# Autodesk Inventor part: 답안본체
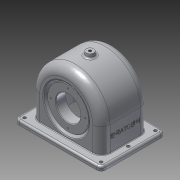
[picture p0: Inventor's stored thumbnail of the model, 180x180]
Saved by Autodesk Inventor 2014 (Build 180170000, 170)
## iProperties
Created: 2015-09
Part Number: 답안본체
Material: 알루미늄 6061
Document SubType Name: Modeling
Designer: basic
Density: 2.71 g/cm^3
Appearance: 알루미늄 - 평지
Mass: 723.087 g
Surface Area: 889.802 cm^2
Volume: 266.822 cm^3
Author: basic
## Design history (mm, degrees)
sketch "스케치2"
  geometry: L1 (57, 47)-(57, 0); L2 (-57, 47)-(-57, 0); L3 (-57, 0)-(57, 0); A1 r 57 centre (0, 47) between (57, 47) and (-57, 47); 2 further points
  constraints: 6 end point, 2 coincident, 2 point on circle, 2 tangent, 1 centre point, 1 midpoint, 1 parallel, 1 perpendicular, 1 vertical
  dimensions: "d1" = 47 distance from line of L3 A1.centre; "d2" = 104 dimension on A1 L3
extrude "돌출1" new body sketch "스케치2" stored distance "d3" = 77; taper "d4" = 0 deg
sketch "스케치3"
  geometry: L1 (114, -77)-(114, 0) reference; L2 (0, 0)-(114, 0) reference; L3 (0, -77)-(0, 0) reference; L4 (114, -77)-(0, -77) reference; L5 (-13, 13.5)-(127, 13.5); L6 (127, 13.5)-(127, -90.5); L7 (127, -90.5)-(-13, -90.5); L8 (-13, -90.5)-(-13, 13.5); 3 further points
  constraints: 8 end point, 2 midpoint, 2 parallel, 1 horizontal, 1 horizontal alignment, 1 perpendicular, 1 vertical alignment
  dimensions: "d6" = 140 distance of L5.start L5.end; "d7" = 104 distance of L5.end L6.end
extrude "돌출2" join sketch "스케치3" distance "d8" = 7; taper "d9" = 0 deg
node "작업 평면1"
sketch "스케치4"
  geometry: C1 r 6 at (-70, -52); 1 further point
  constraints: 1 centre point, 1 coincident
  dimensions: "d11" = 12 diameter of C1
extrude "돌출3" join sketch "스케치4" distance "d12" = 7; taper "d13" = 10 deg
sketch "스케치5"
  geometry: C1 r 31 at (0, -47); A1 r 57 centre (0, -47) between (-57, -47) and (57, -47) reference; 1 further point
  constraints: 1 centre point, 1 coincident
  dimensions: "d14" = 62 diameter of C1
extrude "돌출4" join sketch "스케치5" distance "d15" = 10; taper "d16" = 0 deg
fillet "모깎기1" dims "d17" = 7
sketch "스케치6"
  geometry: L1 (-127, 6.5)-(-127, -83.5) reference; L2 (-120, -90.5)-(6, -90.5) reference; L3 (13, -83.5)-(13, 6.5) reference; 7 further points
  constraints: 4 vertical alignment, 3 horizontal alignment
  dimensions: "d18" = 8 distance from line of L2 point (-119, -82.5); "d19" = 44 distance of point (-119, -38.5) point (-119, -82.5); "d20" = 44 distance of point (-119, 5.5) point (-119, -38.5); "d21" = 8 distance from line of L1 point (-119, 5.5); "d22" = 8 distance from line of L3 point (5, -82.5)
hole "구멍1" sketch "스케치6" at (-119, 5.5), (5, 5.5), (5, -38.5), (5, -82.5), (-119, -82.5), (-119, -38.5) diameter "d23" = 5; stored, may be unused: countersink angle "d27" = 90 deg, drill point angle "d29" = 118 deg; dims "d24" = 6, "d25" = 4, "d26" = 2, "d28" = 8
hole "구멍2" diameter "d32" = 4.459; stored, may be unused: countersink angle "d36" = 90 deg, drill point angle "d38" = 118 deg; dims "d33" = 6, "d34" = 4, "d35" = 2, "d37" = 8, "d39" = 10, "d40" = 10
node "작업 평면2"
sketch "스케치10"
  geometry: L1 (-51, 47)-(-51, 0); L2 (51, 47)-(51, 0); L3 (63, 0)-(-63, 0) reference; L4 (-57, 7)-(-57, 47) reference; A1 r 57 centre (0, 47) between (57, 47) and (-57, 47) reference; A2 r 51 centre (0, 47) between (51, 47) and (-51, 47); 1 further point
  constraints: 4 end point, 2 point on circle, 2 point on line, 2 tangent, 1 centre point, 1 parallel, 1 vertical
  dimensions: "d51" = 51 radius of A2
extrude "돌출6" cut sketch "스케치10" stored distance "d52" = 67; taper "d53" = 0 deg
node "작업 평면3"
sketch "스케치11"
  geometry: C1 r 28 at (0, 47); 1 further point
  constraints: 1 centre point, 1 vertical alignment
  dimensions: "d55" = 56 diameter of C1; "d56" = 47 distance of point (0, 0) C1.centre
extrude "돌출7" join sketch "스케치11" stored distance "d57" = 67; taper "d58" = 40 deg
sketch "스케치13"
  geometry: L1 (-19.5, 75)-(-33.5, 86.747) reference; L2 (-38.5, 104)-(-38.5, 47) reference; L3 (-38.5, 47)-(-38.5, 7) reference; L4 (-38.5, 47)-(-35.5, 47); L5 (-35.5, 47)-(-35.5, 80); L6 (-33.833, 80.5)-(-38.5, 84.416); L7 (-35.5, 80)-(-33.833, 80); L8 (-33.833, 80)-(-33.833, 80.5); 1 further point
  constraints: 10 end point, 3 perpendicular, 1 parallel, 1 point on line
  dimensions: "d64" = 3 distance between parallel lines of L2 L5; "d65" = 5 distance between parallel lines of L1 L6; "d66" = 66 diameter of L7 L4; "d67" = 0.5 distance of L7.end L6.start
revolve "회전1" sketch "스케치13" stored, may be unused: angle "d68" = 90 deg
fillet "모깎기2" dims "d69" = 0.5
fillet "모깎기3" dims "d70" = 0.5
hole "구멍3" diameter "d73" = 40; stored, may be unused: countersink angle "d77" = 90 deg, drill point angle "d79" = 118 deg; dims "d71" = 10, "d72" = 10, "d74" = 6, "d75" = 4, "d76" = 2, "d78" = 8
fillet "모깎기4" dims "d80" = 14
fillet "모깎기5" dims "d81" = 1
fillet "모깎기6" dims "d82" = 9
fillet "모깎기7" dims "d83" = 3
chamfer "모따기1" distance "d85" = 1; stored, may be unused: second distance "d86" = 2, angle "d87" = 45 deg
sketch "스케치14"
  geometry: C1 r 33 at (0, 0) reference; C2 r 21 at (0, 0) reference; A1 r 28 centre (0, 0) between (0, 28) and (28, 0); 3 further points
  constraints: 4 point on circle, 2 horizontal alignment, 2 vertical alignment, 1 centre point, 1 coincident
  dimensions: "d88" = 56 diameter of A1
hole "구멍4" sketch "스케치14" at (0, 28), (28, 0), (-28, 0), (0, -28) diameter "d89" = 2.459; stored, may be unused: countersink angle "d93" = 90 deg, drill point angle "d95" = 118 deg; dims "d90" = 7, "d91" = 4, "d92" = 2, "d94" = 9
sketch "스케치15"
  geometry: C1 r 31 at (0, 0) reference; C2 r 21 at (0, 0) reference; A1 r 24 centre (0, 0) between (0, 24) and (24, 0); 3 further points
  constraints: 4 point on circle, 2 horizontal alignment, 2 vertical alignment, 1 centre point, 1 coincident
  dimensions: "d96" = 48 diameter of A1
hole "구멍5" sketch "스케치15" at (0, 24), (24, 0), (-24, 0), (0, -24) diameter "d97" = 2.459; stored, may be unused: countersink angle "d101" = 90 deg, drill point angle "d103" = 118 deg; dims "d98" = 6, "d99" = 4, "d100" = 2, "d102" = 8
fillet "모깎기9" dims "d104" = 3
fillet "모깎기10" dims "d105" = 3
sketch "스케치16"
  geometry: L1 (0, -14)-(39, -14) reference; L2 (47, -20.5)-(47, 69.5) reference; 2 further points
  constraints: 1 other
  dimensions: "d106" = 38.5 distance from line of L1 point (17, 24.5); "d107" = 30 distance from line of L2 point (17, 24.5)
feature "엠보싱1" sketch "스케치16" dims "d108" = 0.5, "d109" = 0
node "솔리드1"
other parameters: "d46" = -19, "d54" = -19
